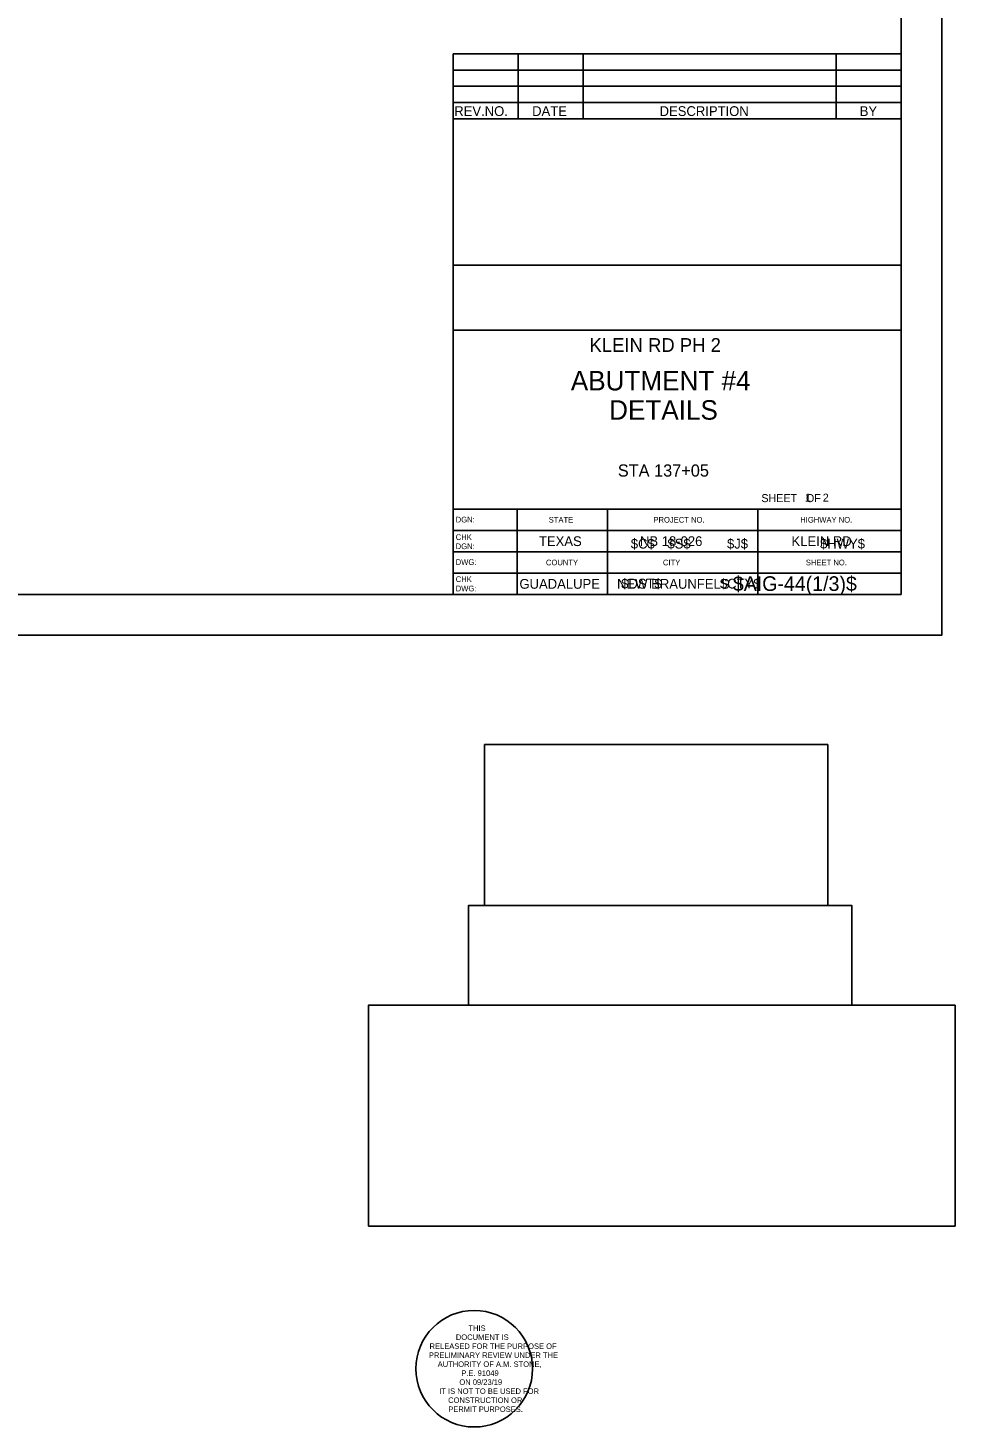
# Model space of a CAD drawing. Extents: x 926 to 1074, y 990 to 1081.
# Drawn here: x 1022.76 to 1034.16, y 990.26 to 1007.47 of the extents above; entities that cross this region are included whole.
import ezdxf

# ---------------------------------------------------------------- set-up
doc = ezdxf.new("R2010")
doc.units = 0
for name, color, linetype in [('BORD_lines_major', 7, 'Continuous'), ('BORD_lines_minor', 7, 'Continuous'), ('BORD_text_large_1', 7, 'Continuous'), ('BORD_text_large_2', 7, 'Continuous'), ('BORD_text_small_1', 7, 'Continuous'), ('BORD_text_small_3', 7, 'Continuous'), ('BORD_text_small_proj', 7, 'Continuous'), ('C-MS-ANNO-TTLB-STMP', 7, 'Continuous'), ('D_BATCH_PLOT', 7, 'Continuous'), ('D_SHEET', 7, 'Continuous'), ('D_SHEET_NUM_CODE', 7, 'Continuous'), ('D_SHEET_TXT_SUB_CODE', 7, 'Continuous'), ('Working Level 1', 7, 'Continuous')]:
    doc.layers.add(name, color=color, linetype=linetype)

msp = doc.modelspace()

# ---------------------------------------------------------------- linework, layer by layer
at = {"layer": 'BORD_lines_major'}
for p, q in [((1033.5, 1000.5), (1033.5, 1021.382)), ((1002.413, 1000.5), (1033.5, 1000.5))]:
    msp.add_line(p, q, dxfattribs=at)
at = {"layer": 'BORD_lines_minor'}
for p, q in [((1027.988, 1007.15), (1033.5, 1007.15)), ((1027.988, 1006.35), (1027.988, 1007.15)), ((1028.788, 1007.15), (1028.788, 1006.35)), ((1029.588, 1007.15), (1029.588, 1006.35)), ((1032.7, 1006.35), (1032.7, 1007.15)), ((1027.988, 1006.95), (1033.5, 1006.95)), ((1027.988, 1006.75), (1033.5, 1006.75)), ((1027.988, 1006.55), (1033.5, 1006.55)), ((1027.988, 1006.35), (1033.5, 1006.35)), ((1027.988, 1006.35), (1027.988, 1004.55)), ((1027.988, 1004.55), (1033.5, 1004.55)), ((1027.988, 1004.55), (1027.988, 1000.5)), ((1027.988, 1003.75), (1033.5, 1003.75)), ((1027.988, 1001.55), (1033.5, 1001.55)), ((1028.776, 1001.55), (1028.776, 1000.5)), ((1029.888, 1001.55), (1029.888, 1000.5)), ((1031.738, 1001.55), (1031.738, 1000.5)), ((1027.988, 1001.287), (1033.5, 1001.287)), ((1027.988, 1001.025), (1033.5, 1001.025)), ((1027.988, 1000.762), (1033.5, 1000.762))]:
    msp.add_line(p, q, dxfattribs=at)
at = {"layer": 'C-MS-ANNO-TTLB-STMP'}
msp.add_circle((1028.248, 990.979), 0.717, dxfattribs=at)
at = {"layer": 'D_BATCH_PLOT'}
msp.add_lwpolyline([(1000, 1000), (1034, 1000), (1034, 1022), (1000, 1022)], close=True, dxfattribs=at)
at = {"layer": 'D_SHEET'}
for p, q in [((1034, 1000), (1034, 1022)), ((1000, 1000), (1034, 1000))]:
    msp.add_line(p, q, dxfattribs=at)
at = {"layer": 'Working Level 1'}
for points in [[(1028.375, 996.675), (1032.596, 996.675), (1032.596, 998.655), (1028.375, 998.655)], [(1028.176, 995.449), (1032.894, 995.449), (1032.894, 996.675), (1028.176, 996.675)], [(1026.947, 992.732), (1034.162, 992.732), (1034.162, 995.449), (1026.947, 995.449)]]:
    msp.add_lwpolyline(points, close=True, dxfattribs=at)

# ---------------------------------------------------------------- texts
at = {"layer": 'BORD_lines_minor'}
for s, p in [('REV.NO.', (1028.002, 1006.385)), ('DATE', (1028.96, 1006.385)), ('DESCRIPTION', (1030.528, 1006.385)), ('BY', (1032.99, 1006.385))]:
    msp.add_text(s, height=0.12, rotation=359.9834, dxfattribs=at).set_placement(p)
msp.add_text('KLEIN RD PH 2', height=0.17, dxfattribs=at).set_placement((1029.665, 1003.483))
at = {"layer": 'BORD_text_large_1'}
for s, p in [('ABUTMENT #4', (1029.436, 1003.01)), ('DETAILS', (1029.907, 1002.65))]:
    msp.add_text(s, height=0.24, dxfattribs=at).set_placement(p)
at = {"layer": 'BORD_text_large_2'}
msp.add_text('STA 137+05', height=0.15, dxfattribs=at).set_placement((1030.014, 1001.95))
at = {"layer": 'BORD_text_small_1'}
msp.add_text('SHEET   OF', height=0.0984, dxfattribs=at).set_placement((1031.78, 1001.636))
at = {"layer": 'BORD_text_small_3'}
msp.add_text('1    2', height=0.0984, dxfattribs=at).set_placement((1032.316, 1001.642))
at = {"layer": 'BORD_text_small_proj'}
for s, height, p in [('DGN:', 0.07, (1028.02, 1001.386)), ('STATE', 0.07, (1029.164, 1001.384)), ('PROJECT NO.', 0.07, (1030.452, 1001.384)), ('HIGHWAY NO.', 0.07, (1032.258, 1001.384)), ('CHK', 0.07, (1028.02, 1001.171)), ('TEXAS', 0.12, (1029.044, 1001.096)), ('KLEIN RD', 0.12, (1032.151, 1001.096)), ('DGN:', 0.07, (1028.02, 1001.058)), ('DWG:', 0.07, (1028.02, 1000.864)), ('COUNTY', 0.07, (1029.13, 1000.859)), ('CITY', 0.07, (1030.569, 1000.859)), ('SHEET NO.', 0.07, (1032.327, 1000.859)), ('CHK', 0.07, (1028.02, 1000.653)), ('GUADALUPE', 0.12, (1028.804, 1000.571)), ('NEW BRAUNFELS', 0.12, (1030.005, 1000.571)), ('DWG:', 0.07, (1028.02, 1000.539))]:
    msp.add_text(s, height=height, rotation=359.9834, dxfattribs=at).set_placement(p)
msp.add_text('NB 18-026', height=0.12, dxfattribs=at).set_placement((1030.287, 1001.096))
at = {"layer": 'C-MS-ANNO-TTLB-STMP'}
for s, height, p in [('DOCUMENT IS', 0.06723, (1028.022, 991.333)), ('THIS', 0.0672, (1028.176, 991.444)), ('RELEASED FOR THE PURPOSE OF', 0.06723, (1027.698, 991.222)), ('PRELIMINARY REVIEW UNDER THE', 0.06723, (1027.69, 991.112)), ('AUTHORITY OF A.M. STONE,', 0.06723, (1027.798, 991.001)), ('P.E. 91049', 0.0672, (1028.089, 990.891)), ('IT IS NOT TO BE USED FOR', 0.06723, (1027.817, 990.669)), ('ON 09/23/19', 0.06723, (1028.065, 990.78)), ('CONSTRUCTION OR', 0.06723, (1027.927, 990.558)), ('PERMIT PURPOSES.', 0.06723, (1027.928, 990.447))]:
    msp.add_text(s, height=height, rotation=360, dxfattribs=at).set_placement(p)
at = {"layer": 'D_SHEET_NUM_CODE'}
msp.add_text('$AIG-44(1/3)$', height=0.18, dxfattribs=at).set_placement((1031.429, 1000.544))
at = {"layer": 'D_SHEET_TXT_SUB_CODE'}
for s, p in [('$C$', (1030.174, 1001.065)), ('$S$', (1030.624, 1001.065)), ('$J$', (1031.357, 1001.065)), ('$HWY$', (1032.501, 1001.065)), ('$DST$', (1030.055, 1000.574)), ('$CTY$', (1031.27, 1000.574))]:
    msp.add_text(s, height=0.12, dxfattribs=at).set_placement(p)

doc.saveas('drawing.dxf')
